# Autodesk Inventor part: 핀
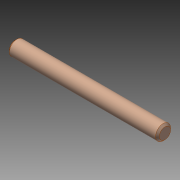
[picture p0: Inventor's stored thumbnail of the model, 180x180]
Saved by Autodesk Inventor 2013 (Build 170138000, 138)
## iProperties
Created: 2023-11
Part Number: 핀
Material: 스테인리스강
Document SubType Name: Modeling
Designer: mdu-01
Density: 1 g/cm^3
Author: mdu-01
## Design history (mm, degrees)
sketch "스케치1"
  geometry: C1 r 2 at (0, 0); 1 further point
  constraints: 1 centre point, 1 coincident
  dimensions: "d0" = 4 diameter of C1
extrude "돌출1" new body sketch "스케치1" stored distance "d1" = 40; taper "d2" = 0 deg
chamfer "모따기1" distance "d3" = 0.5; stored, may be unused: second distance "d4" = 2, angle "d5" = 45 deg
node "솔리드1"
